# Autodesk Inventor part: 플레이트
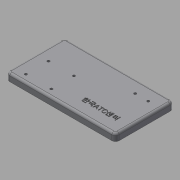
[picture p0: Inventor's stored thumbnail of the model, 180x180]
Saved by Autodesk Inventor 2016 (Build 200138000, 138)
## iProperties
Created: 2018-01
Part Number: 플레이트
Material: 일반
Document SubType Name: Modeling
Designer: mduedu
Density: 1 g/cm^3
Appearance: 기본값
Author: mduedu
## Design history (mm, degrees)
sketch "스케치1"
  geometry: L1 (75, 40)-(-75, 40); L2 (-75, 40)-(-75, -40); L3 (-75, -40)-(75, -40); L4 (75, -40)-(75, 40); L5 (75, 40)-(-75, -40); L6 (-75, 40)-(75, -40); 1 further point
  constraints: 12 end point, 2 midpoint, 2 parallel, 1 horizontal, 1 perpendicular
  dimensions: "d0" = 150 distance of L3.end L2.end; "d1" = 80 distance of L2.end L1.end
extrude "돌출1" new body sketch "스케치1" distance "d2" = 10; taper "d3" = 0 deg
fillet "모깎기1" dims "d4" = 5
fillet "모깎기2" dims "d5" = 3
sketch "스케치2"
  geometry: L1 (-70, 40)-(70, 40) reference; L2 (-75, -35)-(-75, 35) reference; 5 further points
  constraints: 2 horizontal alignment, 2 vertical alignment
  dimensions: "d6" = 10 distance from line of point (-58, 30) L1; "d7" = 35 distance of point (-23, 30) point (-58, 30); "d8" = 31 distance of point (-58, -1) point (-58, 30); "d9" = 17 distance from line of point (-58, 30) L2
sketch "스케치3"
  geometry: 4 further points
  constraints: 4 other
hole "구멍1" sketch "스케치3" at (-23, 30), (-58, -1), (-23, -1), (-58, 30) diameter "d10" = 3.4; stored, may be unused: countersink angle "d14" = 90 deg, drill point angle "d16" = 0 deg; dims "d11" = 6, "d12" = 6.5, "d13" = 3.4, "d15" = 8
sketch "스케치4"
  geometry: L1 (75, 35)-(75, -35) reference; L2 (70, -40)-(-70, -40) reference; 3 further points
  constraints: 1 horizontal alignment
  dimensions: "d17" = 17 distance from line of point (58, -22) L1; "d18" = 18 distance of point (40, -22) point (58, -22); "d19" = 18 distance from line of point (58, -22) L2
sketch "스케치5"
  geometry: 2 further points
  constraints: 2 other
hole "구멍2" sketch "스케치5" at (40, -22), (58, -22) diameter "d20" = 3.4; stored, may be unused: countersink angle "d24" = 90 deg, drill point angle "d26" = 0 deg; dims "d21" = 6, "d22" = 6.5, "d23" = 3.4, "d25" = 8
sketch "스케치6"
  geometry: L1 (75, -35)-(75, 35) reference; L2 (-70, -40)-(70, -40) reference; 2 further points
  constraints: 1 other
  dimensions: "d27" = 40 distance from line of point (35, -20) L1; "d28" = 20 distance from line of point (35, -20) L2
feature "엠보싱1" sketch "스케치6" dims "d0" = 150, "d29" = 0.5, "d30" = 0
node "솔리드1"
